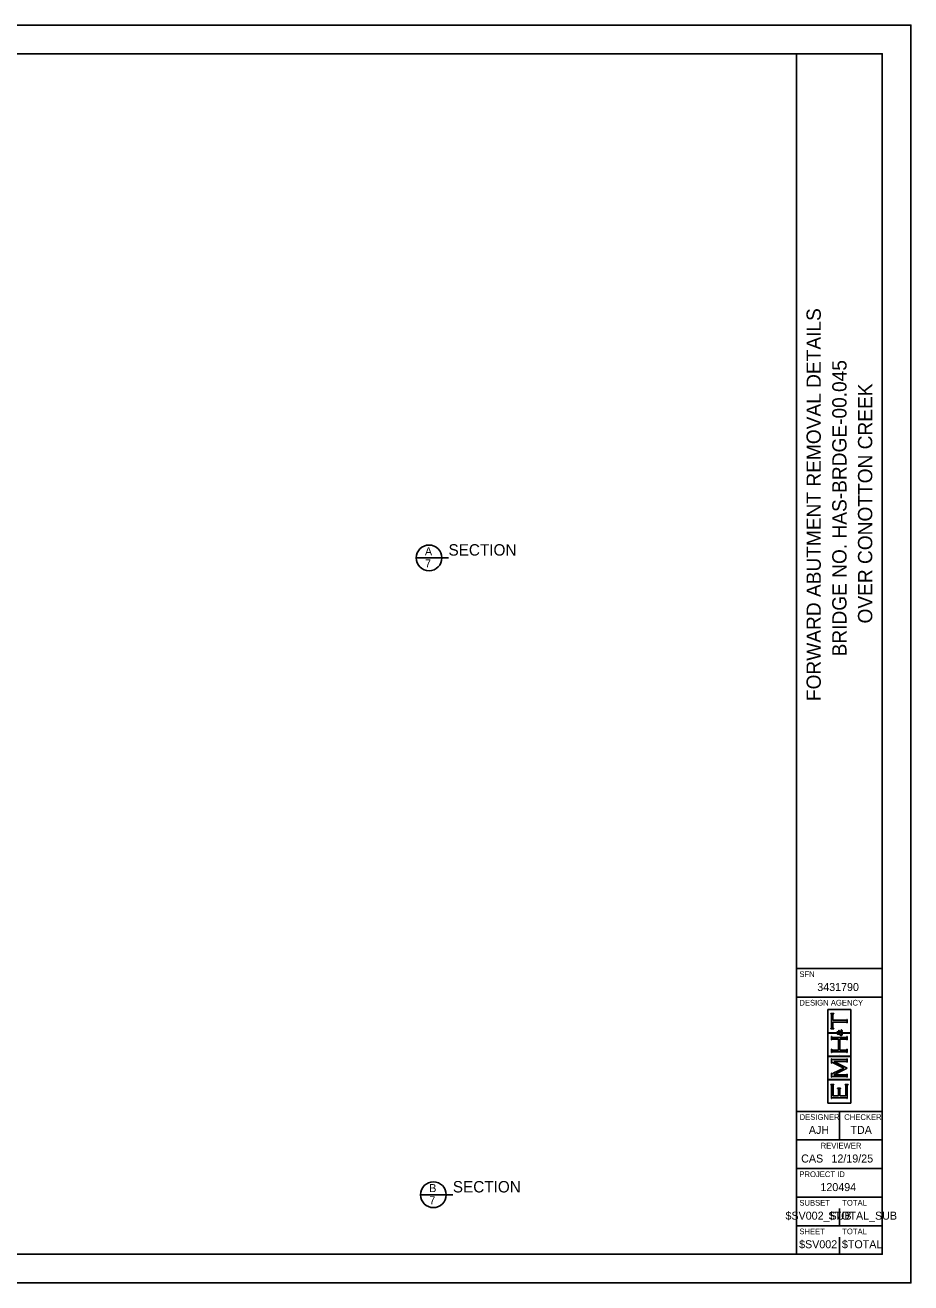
# Model space of a CAD drawing. Extents: x 0 to 34, y 0 to 22.
# Drawn here: x 18.5 to 34, y 0 to 22 of the extents above; entities that cross this region are included whole.
import ezdxf

# ---------------------------------------------------------------- set-up
doc = ezdxf.new("R2010")
doc.units = 0
for name, color, linetype in [('BR_P_Gen_Text', 7, 'Continuous'), ('SH_Border', 7, 'Continuous'), ('SH_Cut_Line', 7, 'Continuous'), ('SH_Data', 7, 'Continuous'), ('SH_Text', 7, 'Continuous')]:
    doc.layers.add(name, color=color, linetype=linetype)

msp = doc.modelspace()

# ---------------------------------------------------------------- linework, layer by layer
at = {"layer": 'SH_Border'}
for p, q in [((32, 0.5), (32, 21.5)), ((32, 5.5), (33.5, 5.5)), ((32, 5), (33.5, 5)), ((32, 3), (33.5, 3)), ((32.75, 3), (32.75, 2.5)), ((32, 2.5), (33.5, 2.5)), ((32, 2), (33.5, 2)), ((32, 1.5), (33.5, 1.5)), ((32, 1), (33.5, 1))]:
    msp.add_line(p, q, dxfattribs=at)
msp.add_lwpolyline([(1.5, 21.5), (33.5, 21.5), (33.5, 0.5), (1.5, 0.5)], close=True, dxfattribs=at)
at = {"layer": 'SH_Cut_Line'}
msp.add_lwpolyline([(0, 0), (34, 0), (34, 22), (0, 22)], close=True, dxfattribs=at)
at = {"layer": 'SH_Data'}
for p, q in [((32.952, 4.779), (32.547, 4.779)), ((32.547, 4.779), (32.547, 4.375)), ((32.598, 4.704), (32.598, 4.711)), ((32.598, 4.711), (32.65, 4.711)), ((32.603, 4.703), (32.598, 4.704)), ((32.606, 4.701), (32.603, 4.703)), ((32.608, 4.699), (32.606, 4.701)), ((32.61, 4.696), (32.608, 4.699)), ((32.611, 4.692), (32.61, 4.696)), ((32.611, 4.687), (32.611, 4.692)), ((32.611, 4.468), (32.611, 4.687)), ((32.638, 4.696), (32.637, 4.692)), ((32.637, 4.692), (32.637, 4.687)), ((32.637, 4.687), (32.637, 4.593)), ((32.64, 4.699), (32.638, 4.696)), ((32.642, 4.701), (32.64, 4.699)), ((32.645, 4.703), (32.642, 4.701)), ((32.65, 4.704), (32.645, 4.703)), ((32.65, 4.711), (32.65, 4.704)), ((32.952, 4.375), (32.952, 4.779)), ((32.598, 4.45), (32.603, 4.451)), ((32.598, 4.444), (32.598, 4.45)), ((32.65, 4.444), (32.598, 4.444)), ((32.603, 4.451), (32.606, 4.453)), ((32.606, 4.453), (32.608, 4.455)), ((32.608, 4.455), (32.61, 4.458)), ((32.61, 4.458), (32.611, 4.462)), ((32.611, 4.462), (32.611, 4.468)), ((32.637, 4.593), (32.864, 4.593)), ((32.864, 4.561), (32.637, 4.561)), ((32.637, 4.561), (32.637, 4.468)), ((32.637, 4.468), (32.637, 4.462)), ((32.637, 4.462), (32.638, 4.458)), ((32.638, 4.458), (32.64, 4.455)), ((32.64, 4.455), (32.642, 4.453)), ((32.642, 4.453), (32.645, 4.451)), ((32.645, 4.451), (32.65, 4.45)), ((32.65, 4.45), (32.65, 4.444)), ((32.738, 4.393), (32.738, 4.422)), ((32.738, 4.422), (32.741, 4.422)), ((32.741, 4.422), (32.741, 4.418)), ((32.741, 4.418), (32.742, 4.415)), ((32.742, 4.415), (32.743, 4.413)), ((32.743, 4.413), (32.745, 4.411)), ((32.745, 4.411), (32.749, 4.408)), ((32.749, 4.408), (32.756, 4.404)), ((32.756, 4.404), (32.763, 4.4)), ((32.763, 4.4), (32.77, 4.396)), ((32.779, 4.423), (32.781, 4.426)), ((32.782, 4.422), (32.779, 4.423)), ((32.781, 4.426), (32.787, 4.424)), ((32.785, 4.421), (32.782, 4.422)), ((32.784, 4.398), (32.786, 4.401)), ((32.786, 4.419), (32.785, 4.421)), ((32.788, 4.417), (32.786, 4.419)), ((32.786, 4.401), (32.788, 4.404)), ((32.787, 4.424), (32.792, 4.421)), ((32.789, 4.414), (32.788, 4.417)), ((32.788, 4.404), (32.789, 4.408)), ((32.789, 4.411), (32.789, 4.414)), ((32.789, 4.408), (32.789, 4.411)), ((32.792, 4.421), (32.795, 4.418)), ((32.795, 4.418), (32.798, 4.414)), ((32.798, 4.414), (32.799, 4.41)), ((32.799, 4.401), (32.798, 4.397)), ((32.799, 4.41), (32.799, 4.405)), ((32.799, 4.405), (32.799, 4.401)), ((32.864, 4.593), (32.869, 4.593)), ((32.87, 4.561), (32.864, 4.561)), ((32.869, 4.593), (32.873, 4.594)), ((32.874, 4.56), (32.87, 4.561)), ((32.873, 4.594), (32.876, 4.596)), ((32.876, 4.559), (32.874, 4.56)), ((32.876, 4.596), (32.878, 4.597)), ((32.878, 4.557), (32.876, 4.559)), ((32.878, 4.597), (32.88, 4.601)), ((32.88, 4.553), (32.878, 4.557)), ((32.88, 4.601), (32.881, 4.606)), ((32.881, 4.548), (32.88, 4.553)), ((32.881, 4.606), (32.888, 4.606)), ((32.888, 4.548), (32.881, 4.548)), ((32.888, 4.606), (32.888, 4.548)), ((32.547, 4.375), (32.696, 4.375)), ((32.696, 4.369), (32.547, 4.369)), ((32.547, 4.369), (32.547, 3.965)), ((32.611, 4.249), (32.611, 4.307)), ((32.611, 4.307), (32.617, 4.307)), ((32.617, 4.249), (32.611, 4.249)), ((32.617, 4.307), (32.619, 4.302)), ((32.618, 4.254), (32.617, 4.249)), ((32.62, 4.258), (32.618, 4.254)), ((32.619, 4.302), (32.62, 4.298)), ((32.62, 4.298), (32.623, 4.297)), ((32.623, 4.26), (32.62, 4.258)), ((32.623, 4.297), (32.625, 4.295)), ((32.625, 4.261), (32.623, 4.26)), ((32.625, 4.295), (32.629, 4.294)), ((32.629, 4.262), (32.625, 4.261)), ((32.629, 4.294), (32.635, 4.294)), ((32.635, 4.262), (32.629, 4.262)), ((32.635, 4.294), (32.864, 4.294)), ((32.732, 4.262), (32.635, 4.262)), ((32.696, 4.375), (32.696, 4.369)), ((32.703, 4.379), (32.705, 4.383)), ((32.703, 4.373), (32.703, 4.379)), ((32.703, 4.368), (32.703, 4.373)), ((32.705, 4.363), (32.703, 4.368)), ((32.705, 4.383), (32.708, 4.387)), ((32.708, 4.358), (32.705, 4.363)), ((32.708, 4.387), (32.711, 4.39)), ((32.709, 4.379), (32.708, 4.376)), ((32.708, 4.376), (32.708, 4.373)), ((32.708, 4.373), (32.708, 4.369)), ((32.708, 4.369), (32.71, 4.366)), ((32.712, 4.353), (32.708, 4.358)), ((32.712, 4.381), (32.709, 4.379)), ((32.71, 4.366), (32.712, 4.364)), ((32.711, 4.39), (32.715, 4.392)), ((32.714, 4.383), (32.712, 4.381)), ((32.712, 4.364), (32.715, 4.362)), ((32.718, 4.35), (32.712, 4.353)), ((32.716, 4.384), (32.714, 4.383)), ((32.715, 4.392), (32.72, 4.392)), ((32.715, 4.362), (32.718, 4.361)), ((32.72, 4.384), (32.716, 4.384)), ((32.718, 4.361), (32.721, 4.361)), ((32.726, 4.35), (32.718, 4.35)), ((32.72, 4.392), (32.725, 4.392)), ((32.724, 4.384), (32.72, 4.384)), ((32.721, 4.361), (32.723, 4.361)), ((32.723, 4.361), (32.725, 4.362)), ((32.728, 4.382), (32.724, 4.384)), ((32.725, 4.392), (32.729, 4.39)), ((32.725, 4.362), (32.728, 4.362)), ((32.729, 4.35), (32.726, 4.35)), ((32.731, 4.38), (32.728, 4.382)), ((32.728, 4.362), (32.731, 4.363)), ((32.729, 4.39), (32.732, 4.387)), ((32.731, 4.35), (32.729, 4.35)), ((32.734, 4.377), (32.731, 4.38)), ((32.731, 4.363), (32.735, 4.365)), ((32.734, 4.351), (32.731, 4.35)), ((32.732, 4.387), (32.736, 4.383)), ((32.732, 4.072), (32.732, 4.262)), ((32.737, 4.372), (32.734, 4.377)), ((32.737, 4.352), (32.734, 4.351)), ((32.735, 4.365), (32.74, 4.367)), ((32.736, 4.383), (32.74, 4.378)), ((32.74, 4.367), (32.737, 4.372)), ((32.741, 4.353), (32.737, 4.352)), ((32.741, 4.393), (32.738, 4.393)), ((32.74, 4.378), (32.744, 4.369)), ((32.742, 4.396), (32.741, 4.395)), ((32.741, 4.395), (32.741, 4.393)), ((32.746, 4.355), (32.741, 4.353)), ((32.743, 4.397), (32.742, 4.396)), ((32.745, 4.399), (32.743, 4.397)), ((32.744, 4.369), (32.754, 4.375)), ((32.746, 4.399), (32.745, 4.399)), ((32.748, 4.399), (32.746, 4.399)), ((32.752, 4.344), (32.746, 4.355)), ((32.755, 4.399), (32.748, 4.399)), ((32.756, 4.36), (32.751, 4.357)), ((32.751, 4.357), (32.754, 4.352)), ((32.757, 4.337), (32.752, 4.344)), ((32.754, 4.375), (32.764, 4.381)), ((32.754, 4.352), (32.757, 4.348)), ((32.763, 4.395), (32.755, 4.399)), ((32.761, 4.363), (32.756, 4.36)), ((32.757, 4.348), (32.761, 4.345)), ((32.763, 4.333), (32.757, 4.337)), ((32.864, 4.262), (32.759, 4.262)), ((32.759, 4.262), (32.759, 4.072)), ((32.764, 4.365), (32.761, 4.363)), ((32.761, 4.345), (32.765, 4.343)), ((32.772, 4.387), (32.763, 4.395)), ((32.768, 4.329), (32.763, 4.333)), ((32.764, 4.381), (32.772, 4.387)), ((32.768, 4.367), (32.764, 4.365)), ((32.765, 4.343), (32.769, 4.341)), ((32.774, 4.372), (32.768, 4.367)), ((32.774, 4.327), (32.768, 4.329)), ((32.769, 4.341), (32.773, 4.341)), ((32.77, 4.396), (32.776, 4.391)), ((32.773, 4.341), (32.778, 4.341)), ((32.782, 4.378), (32.774, 4.372)), ((32.779, 4.327), (32.774, 4.327)), ((32.776, 4.391), (32.781, 4.395)), ((32.778, 4.341), (32.782, 4.343)), ((32.785, 4.327), (32.779, 4.327)), ((32.781, 4.395), (32.784, 4.398)), ((32.786, 4.373), (32.782, 4.378)), ((32.782, 4.343), (32.786, 4.346)), ((32.79, 4.329), (32.785, 4.327)), ((32.791, 4.386), (32.786, 4.381)), ((32.786, 4.381), (32.791, 4.376)), ((32.788, 4.369), (32.786, 4.373)), ((32.786, 4.346), (32.789, 4.349)), ((32.79, 4.367), (32.788, 4.369)), ((32.789, 4.349), (32.791, 4.353)), ((32.791, 4.364), (32.79, 4.367)), ((32.793, 4.334), (32.79, 4.329)), ((32.794, 4.39), (32.791, 4.386)), ((32.791, 4.376), (32.795, 4.37)), ((32.791, 4.361), (32.791, 4.364)), ((32.791, 4.359), (32.791, 4.361)), ((32.791, 4.353), (32.791, 4.359)), ((32.797, 4.338), (32.793, 4.334)), ((32.796, 4.394), (32.794, 4.39)), ((32.795, 4.37), (32.797, 4.366)), ((32.798, 4.397), (32.796, 4.394)), ((32.797, 4.366), (32.798, 4.361)), ((32.799, 4.344), (32.797, 4.338)), ((32.798, 4.361), (32.799, 4.357)), ((32.803, 4.369), (32.799, 4.375)), ((32.799, 4.375), (32.952, 4.375)), ((32.799, 4.357), (32.799, 4.352)), ((32.799, 4.352), (32.799, 4.344)), ((32.952, 4.369), (32.803, 4.369)), ((32.864, 4.294), (32.869, 4.294)), ((32.87, 4.262), (32.864, 4.262)), ((32.869, 4.294), (32.873, 4.295)), ((32.874, 4.261), (32.87, 4.262)), ((32.873, 4.295), (32.876, 4.297)), ((32.876, 4.26), (32.874, 4.261)), ((32.876, 4.297), (32.878, 4.298)), ((32.878, 4.258), (32.876, 4.26)), ((32.878, 4.298), (32.88, 4.302)), ((32.88, 4.254), (32.878, 4.258)), ((32.88, 4.302), (32.881, 4.307)), ((32.881, 4.249), (32.88, 4.254)), ((32.881, 4.307), (32.888, 4.307)), ((32.888, 4.249), (32.881, 4.249)), ((32.888, 4.307), (32.888, 4.249)), ((32.952, 3.965), (32.952, 4.369)), ((32.547, 3.965), (32.952, 3.965)), ((32.611, 4.027), (32.611, 4.085)), ((32.611, 4.085), (32.617, 4.085)), ((32.617, 4.027), (32.611, 4.027)), ((32.617, 4.085), (32.619, 4.08)), ((32.618, 4.032), (32.617, 4.027)), ((32.62, 4.036), (32.618, 4.032)), ((32.619, 4.08), (32.62, 4.076)), ((32.62, 4.076), (32.623, 4.074)), ((32.623, 4.037), (32.62, 4.036)), ((32.623, 4.074), (32.625, 4.073)), ((32.625, 4.039), (32.623, 4.037)), ((32.625, 4.073), (32.629, 4.072)), ((32.629, 4.04), (32.625, 4.039)), ((32.629, 4.072), (32.635, 4.072)), ((32.635, 4.04), (32.629, 4.04)), ((32.635, 4.072), (32.732, 4.072)), ((32.864, 4.04), (32.635, 4.04)), ((32.75, 4), (32.75, 4)), ((32.759, 4.072), (32.864, 4.072)), ((32.864, 4.072), (32.87, 4.072)), ((32.87, 4.04), (32.864, 4.04)), ((32.87, 4.072), (32.874, 4.073)), ((32.874, 4.039), (32.87, 4.04)), ((32.874, 4.073), (32.876, 4.074)), ((32.876, 4.038), (32.874, 4.039)), ((32.876, 4.074), (32.878, 4.076)), ((32.878, 4.036), (32.876, 4.038)), ((32.878, 4.076), (32.88, 4.08)), ((32.88, 4.032), (32.878, 4.036)), ((32.88, 4.08), (32.881, 4.085)), ((32.881, 4.027), (32.88, 4.032)), ((32.881, 4.085), (32.888, 4.085)), ((32.888, 4.027), (32.881, 4.027)), ((32.888, 4.085), (32.888, 4.027)), ((32.952, 3.959), (32.547, 3.959)), ((32.547, 3.959), (32.547, 3.555)), ((32.611, 3.845), (32.611, 3.918)), ((32.611, 3.918), (32.617, 3.918)), ((32.617, 3.845), (32.611, 3.845)), ((32.617, 3.918), (32.619, 3.912)), ((32.62, 3.852), (32.617, 3.845)), ((32.619, 3.912), (32.62, 3.909)), ((32.62, 3.909), (32.623, 3.907)), ((32.622, 3.855), (32.62, 3.852)), ((32.626, 3.855), (32.622, 3.855)), ((32.623, 3.907), (32.625, 3.905)), ((32.625, 3.905), (32.629, 3.905)), ((32.629, 3.855), (32.626, 3.855)), ((32.629, 3.905), (32.635, 3.905)), ((32.633, 3.853), (32.629, 3.855)), ((32.64, 3.85), (32.633, 3.853)), ((32.635, 3.905), (32.864, 3.905)), ((32.825, 3.757), (32.64, 3.85)), ((32.641, 3.665), (32.825, 3.757)), ((32.864, 3.873), (32.654, 3.873)), ((32.654, 3.873), (32.888, 3.755)), ((32.888, 3.755), (32.654, 3.638)), ((32.864, 3.905), (32.869, 3.905)), ((32.87, 3.873), (32.864, 3.873)), ((32.869, 3.905), (32.873, 3.905)), ((32.874, 3.872), (32.87, 3.873)), ((32.873, 3.905), (32.876, 3.907)), ((32.876, 3.87), (32.874, 3.872)), ((32.876, 3.907), (32.878, 3.909)), ((32.878, 3.869), (32.876, 3.87)), ((32.878, 3.909), (32.88, 3.912)), ((32.88, 3.865), (32.878, 3.869)), ((32.88, 3.912), (32.881, 3.918)), ((32.881, 3.86), (32.88, 3.865)), ((32.881, 3.918), (32.888, 3.918)), ((32.888, 3.86), (32.881, 3.86)), ((32.888, 3.918), (32.888, 3.86)), ((32.952, 3.555), (32.952, 3.959)), ((32.547, 3.555), (32.952, 3.555)), ((32.952, 3.549), (32.547, 3.549)), ((32.547, 3.549), (32.547, 3.145)), ((32.611, 3.596), (32.611, 3.668)), ((32.611, 3.668), (32.617, 3.668)), ((32.617, 3.596), (32.611, 3.596)), ((32.617, 3.668), (32.62, 3.662)), ((32.618, 3.602), (32.617, 3.596)), ((32.62, 3.605), (32.618, 3.602)), ((32.62, 3.662), (32.622, 3.658)), ((32.623, 3.607), (32.62, 3.605)), ((32.622, 3.658), (32.626, 3.658)), ((32.625, 3.609), (32.623, 3.607)), ((32.629, 3.609), (32.625, 3.609)), ((32.626, 3.658), (32.627, 3.658)), ((32.627, 3.658), (32.633, 3.661)), ((32.635, 3.609), (32.629, 3.609)), ((32.633, 3.661), (32.641, 3.665)), ((32.864, 3.609), (32.635, 3.609)), ((32.654, 3.638), (32.864, 3.638)), ((32.864, 3.638), (32.869, 3.638)), ((32.87, 3.609), (32.864, 3.609)), ((32.869, 3.638), (32.873, 3.639)), ((32.874, 3.609), (32.87, 3.609)), ((32.873, 3.639), (32.876, 3.641)), ((32.876, 3.607), (32.874, 3.609)), ((32.876, 3.641), (32.878, 3.643)), ((32.878, 3.605), (32.876, 3.607)), ((32.878, 3.643), (32.88, 3.646)), ((32.88, 3.602), (32.878, 3.605)), ((32.88, 3.646), (32.881, 3.651)), ((32.881, 3.596), (32.88, 3.602)), ((32.881, 3.651), (32.888, 3.651)), ((32.888, 3.596), (32.881, 3.596)), ((32.888, 3.651), (32.888, 3.596)), ((32.952, 3.145), (32.952, 3.549)), ((32.598, 3.462), (32.598, 3.469)), ((32.598, 3.469), (32.65, 3.469)), ((32.603, 3.461), (32.598, 3.462)), ((32.606, 3.459), (32.603, 3.461)), ((32.608, 3.457), (32.606, 3.459)), ((32.61, 3.455), (32.608, 3.457)), ((32.611, 3.451), (32.61, 3.455)), ((32.611, 3.445), (32.611, 3.451)), ((32.611, 3.225), (32.611, 3.445)), ((32.64, 3.457), (32.638, 3.455)), ((32.638, 3.455), (32.638, 3.451)), ((32.638, 3.451), (32.638, 3.445)), ((32.638, 3.445), (32.638, 3.27)), ((32.642, 3.459), (32.64, 3.457)), ((32.645, 3.461), (32.642, 3.459)), ((32.65, 3.462), (32.645, 3.461)), ((32.65, 3.469), (32.65, 3.462)), ((32.719, 3.402), (32.719, 3.408)), ((32.719, 3.408), (32.772, 3.408)), ((32.724, 3.401), (32.719, 3.402)), ((32.728, 3.399), (32.724, 3.401)), ((32.729, 3.396), (32.728, 3.399)), ((32.731, 3.394), (32.729, 3.396)), ((32.732, 3.39), (32.731, 3.394)), ((32.732, 3.384), (32.732, 3.39)), ((32.732, 3.27), (32.732, 3.384)), ((32.76, 3.394), (32.759, 3.39)), ((32.759, 3.39), (32.759, 3.384)), ((32.759, 3.384), (32.759, 3.27)), ((32.761, 3.396), (32.76, 3.394)), ((32.763, 3.399), (32.761, 3.396)), ((32.767, 3.401), (32.763, 3.399)), ((32.772, 3.402), (32.767, 3.401)), ((32.772, 3.408), (32.772, 3.402)), ((32.848, 3.465), (32.848, 3.472)), ((32.848, 3.472), (32.901, 3.472)), ((32.853, 3.464), (32.848, 3.465)), ((32.857, 3.462), (32.853, 3.464)), ((32.859, 3.46), (32.857, 3.462)), ((32.86, 3.458), (32.859, 3.46)), ((32.861, 3.453), (32.86, 3.458)), ((32.861, 3.448), (32.861, 3.453)), ((32.861, 3.27), (32.861, 3.448)), ((32.889, 3.457), (32.888, 3.453)), ((32.888, 3.453), (32.888, 3.448)), ((32.888, 3.448), (32.888, 3.225)), ((32.891, 3.46), (32.889, 3.457)), ((32.892, 3.462), (32.891, 3.46)), ((32.896, 3.464), (32.892, 3.462)), ((32.901, 3.465), (32.896, 3.464)), ((32.901, 3.472), (32.901, 3.465)), ((32.547, 3.145), (32.952, 3.145)), ((32.617, 3.225), (32.611, 3.225)), ((32.619, 3.23), (32.617, 3.225)), ((32.62, 3.234), (32.619, 3.23)), ((32.623, 3.235), (32.62, 3.234)), ((32.625, 3.237), (32.623, 3.235)), ((32.629, 3.238), (32.625, 3.237)), ((32.635, 3.238), (32.629, 3.238)), ((32.864, 3.238), (32.635, 3.238)), ((32.638, 3.27), (32.732, 3.27)), ((32.759, 3.27), (32.861, 3.27)), ((32.87, 3.238), (32.864, 3.238)), ((32.874, 3.237), (32.87, 3.238)), ((32.876, 3.235), (32.874, 3.237)), ((32.878, 3.234), (32.876, 3.235)), ((32.88, 3.23), (32.878, 3.234)), ((32.881, 3.225), (32.88, 3.23)), ((32.888, 3.225), (32.881, 3.225)), ((32.75, 1), (32.75, 1.3)), ((32.375, 0.675), (32.375, 0.675)), ((32.75, 0.5), (32.75, 0.8))]:
    msp.add_line(p, q, dxfattribs=at)
at = {"layer": 'SH_Text'}
for p, q in [((25.346, 12.681), (25.911, 12.681)), ((25.421, 1.541), (25.987, 1.541))]:
    msp.add_line(p, q, dxfattribs=at)
for centre in [(25.571, 12.681), (25.646, 1.541)]:
    msp.add_circle(centre, 0.225, dxfattribs=at)

# ---------------------------------------------------------------- texts
at = {"layer": 'BR_P_Gen_Text'}
for p in [(25.911, 12.721), (25.987, 1.581)]:
    msp.add_text('SECTION', height=0.2, dxfattribs=at).set_placement(p)
at = {"layer": 'SH_Data'}
for s, p in [('FORWARD ABUTMENT REMOVAL DETAILS', (32.425, 10.176)), ('BRIDGE NO. HAS-BRDGE-00.045', (32.875, 10.958)), ('OVER CONOTTON CREEK', (33.325, 11.534))]:
    msp.add_text(s, height=0.25, rotation=90, dxfattribs=at).set_placement(p)
for s, height, p in [('SFN', 0.1, (32.05, 5.35)), ('3431790', 0.14, (32.363, 5.105)), ('DESIGN AGENCY', 0.1, (32.05, 4.85)), ('DESIGNER', 0.1, (32.054, 2.85)), ('CHECKER', 0.1, (32.835, 2.85)), ('AJH', 0.14, (32.215, 2.605)), ('TDA', 0.14, (32.943, 2.605)), ('REVIEWER', 0.1, (32.422, 2.35)), ('CAS', 0.14, (32.081, 2.105)), ('12/19/25', 0.14, (32.611, 2.105)), ('PROJECT ID', 0.1, (32.05, 1.85)), ('120494', 0.14, (32.418, 1.605)), ('SUBSET', 0.1, (32.05, 1.35)), ('TOTAL', 0.1, (32.8, 1.35)), ('$SV002_SUB', 0.14, (31.807, 1.105)), ('$TOTAL_SUB', 0.14, (32.562, 1.105)), ('SHEET', 0.1, (32.05, 0.85)), ('TOTAL', 0.1, (32.8, 0.85)), ('$SV002', 0.14, (32.045, 0.605)), ('$TOTAL', 0.14, (32.794, 0.605))]:
    msp.add_text(s, height=height, dxfattribs=at).set_placement(p)
at = {"layer": 'SH_Text'}
for s, p in [('A', (25.499, 12.727)), ('7', (25.501, 12.514)), ('B', (25.575, 1.587)), ('7', (25.576, 1.375))]:
    msp.add_text(s, height=0.14, dxfattribs=at).set_placement(p)

doc.saveas('drawing.dxf')
